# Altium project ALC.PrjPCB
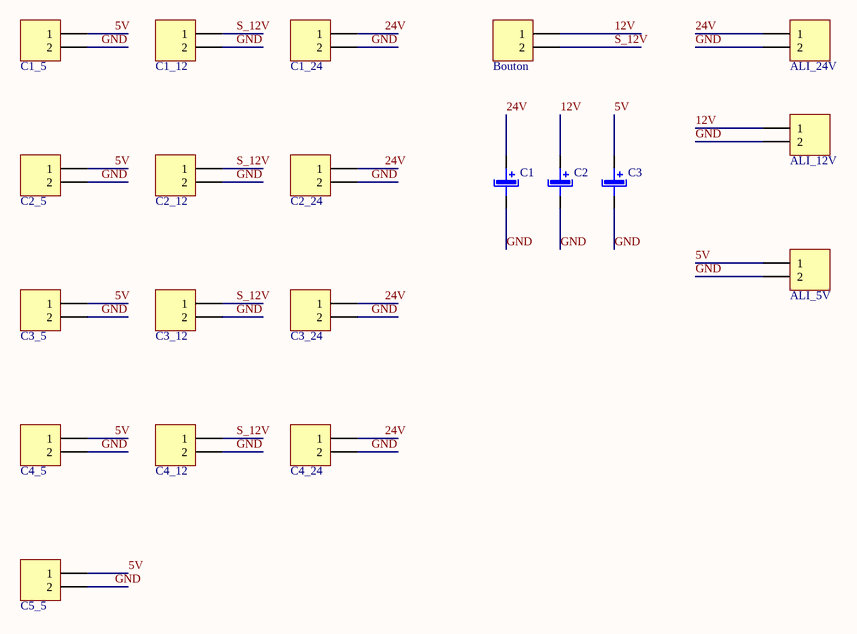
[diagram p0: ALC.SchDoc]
1 sheet, 20 parts. Net scope: global (net labels, ports and power ports of the same name join across sheets).
Board file: ALC.PcbDoc

## Sheet ALC.SchDoc
size A4

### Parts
ALI_5V  Molex_2  [Header_2Ecam]  (value not drawn)
ALI_12V  Molex_2  [Header_2Ecam]  (value not drawn)
ALI_24V  Molex_2  [Header_2Ecam]  (value not drawn)
Bouton  Molex_2  [Header_2Ecam]  (value not drawn)
C1  Cond pol radial  [CAPPR2-5x6.8]  (value not drawn)
C1_5  Molex_2  [Header_2Ecam]  (value not drawn)
C1_12  Molex_2  [Header_2Ecam]  (value not drawn)
C1_24  Molex_2  [Header_2Ecam]  (value not drawn)
C2  Cond pol radial  [CAPPR2-5x6.8]  (value not drawn)
C2_5  Molex_2  [Header_2Ecam]  (value not drawn)
C2_12  Molex_2  [Header_2Ecam]  (value not drawn)
C2_24  Molex_2  [Header_2Ecam]  (value not drawn)
C3  Cond pol radial  [CAPPR2-5x6.8]  (value not drawn)
C3_5  Molex_2  [Header_2Ecam]  (value not drawn)
C3_12  Molex_2  [Header_2Ecam]  (value not drawn)
C3_24  Molex_2  [Header_2Ecam]  (value not drawn)
C4_5  Molex_2  [Header_2Ecam]  (value not drawn)
C4_12  Molex_2  [Header_2Ecam]  (value not drawn)
C4_24  Molex_2  [Header_2Ecam]  (value not drawn)
C5_5  Molex_2  [Header_2Ecam]  (value not drawn)

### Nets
5V: ALI_5V.1 C1_5.1 C2_5.1 C3.1(+) C3_5.1 C4_5.1 C5_5.1
12V: ALI_12V.1 Bouton.1 C2.1(+)
24V: ALI_24V.1 C1.1(+) C1_24.1 C2_24.1 C3_24.1 C4_24.1
GND: ALI_5V.2 ALI_12V.2 ALI_24V.2 C1.2(-) C1_5.2 C1_12.2 C1_24.2 C2.2(-) C2_5.2 C2_12.2 C2_24.2 C3.2(-) C3_5.2 C3_12.2 C3_24.2 C4_5.2 C4_12.2 C4_24.2 C5_5.2
S_12V: Bouton.2 C1_12.1 C2_12.1 C3_12.1 C4_12.1

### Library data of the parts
ALI_5V ALI_12V ALI_24V Bouton = Molex_2: Header, 2-pin
C1-C3 = Cond pol radial: Condensateur polatisé; Type: Condensateur polarisé debout
C1_5 C1_12 C1_24 C2_5 C2_12 C2_24 C3_5 C3_12 C3_24 C4_5 C4_12 C4_24 C5_5 = Molex_2: Header, 2-pin; Type: Connecteur à vis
